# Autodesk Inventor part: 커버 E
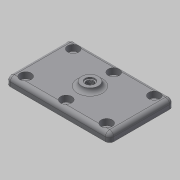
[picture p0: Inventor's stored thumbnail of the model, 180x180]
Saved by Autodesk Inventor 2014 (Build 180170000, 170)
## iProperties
Created: 2020-04
Part Number: 커버 E
Material: 알루미늄 6061
Document SubType Name: Modeling
Designer: mduedu
Density: 2.71 g/cm^3
Appearance: Default
Mass: 58.8274 g
Surface Area: 89.9597 cm^2
Volume: 21.7075 cm^3
Author: mduedu
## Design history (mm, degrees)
sketch "스케치1"
  geometry: L1 (37, 23)-(-37, 23); L2 (-37, 23)-(-37, -23); L3 (-37, -23)-(37, -23); L4 (37, -23)-(37, 23); L5 (37, 23)-(-37, -23); L6 (-37, 23)-(37, -23); 1 further point
  constraints: 12 end point, 2 midpoint, 2 parallel, 1 horizontal, 1 perpendicular
  dimensions: "d0" = 74 distance of L3.end L2.end; "d1" = 46 distance of L2.end L1.end
extrude "돌출1" new body sketch "스케치1" distance "d2" = 6; taper "d3" = 0 deg
sketch "스케치2"
  geometry: C1 r 6 at (0, 0); 1 further point
  constraints: 1 centre point, 1 coincident
  dimensions: "d4" = 12 diameter of C1
extrude "돌출2" join sketch "스케치2" distance "d5" = 3; taper "d6" = 0 deg
fillet "모깎기1" dims "d7" = 3
fillet "모깎기2" dims "d8" = 3
fillet "모깎기3" dims "d9" = 3
sketch "스케치3"
  geometry: L1 (-30, -13)-(30, -13); L2 (30, -13)-(30, 13); L3 (30, 13)-(-30, 13); L4 (-30, 13)-(-30, -13); L5 (-30, -13)-(30, 13); L6 (30, -13)-(-30, 13); 1 further point
  constraints: 12 end point, 2 midpoint, 2 parallel, 1 horizontal, 1 perpendicular
  dimensions: "d10" = 60 distance of L3.end L2.end; "d11" = 26 distance of L2.end L1.end
extrude "돌출3" join sketch "스케치3" distance "d12" = 2; taper "d13" = 0 deg
fillet "모깎기4" dims "d14" = 3
chamfer "모따기1" distance "d15" = 0.5; stored, may be unused: second distance "d16" = 2, angle "d17" = 45 deg
sketch "스케치4"
  geometry: L1 (-29, -17)-(29, -17); L2 (29, -17)-(29, 17); L3 (29, 17)-(-29, 17); L4 (-29, 17)-(-29, -17); L5 (-29, -17)-(29, 17); L6 (29, -17)-(-29, 17); 7 further points
  constraints: 12 end point, 4 coincident, 4 midpoint, 2 parallel, 1 horizontal, 1 perpendicular
  dimensions: "d18" = 58 distance of L3.end L2.end; "d19" = 34 distance of L2.end L1.end
hole "구멍1" sketch "스케치4" at (-29, 17), (-29, -17), (29, -17), (29, 17), (0, 17), (0, -17) diameter "d20" = 4.5; stored, may be unused: countersink angle "d24" = 90 deg, drill point angle "d26" = 118 deg; dims "d21" = 6, "d22" = 8, "d23" = 4.4, "d25" = 8
hole "구멍2" diameter "d29" = 5.188; stored, may be unused: countersink angle "d33" = 90 deg, drill point angle "d35" = 118 deg; dims "d27" = 10, "d28" = 10, "d30" = 6, "d31" = 8, "d32" = 4.4, "d34" = 8
sketch "스케치5"
  geometry: C1 r 3.5 at (0, 0); 1 further point
  constraints: 1 centre point, 1 coincident
  dimensions: "d36" = 7 diameter of C1
extrude "돌출4" cut sketch "스케치5" distance "d37" = 1; taper "d38" = 0 deg
node "솔리드1"
